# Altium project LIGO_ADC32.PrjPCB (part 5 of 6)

## Sheet AD32_Bipolar2.SchDoc: Dual Analog Supply
size B; Engineer: Daniel Sigg; SheetNumber: 11; SheetTotal: 17
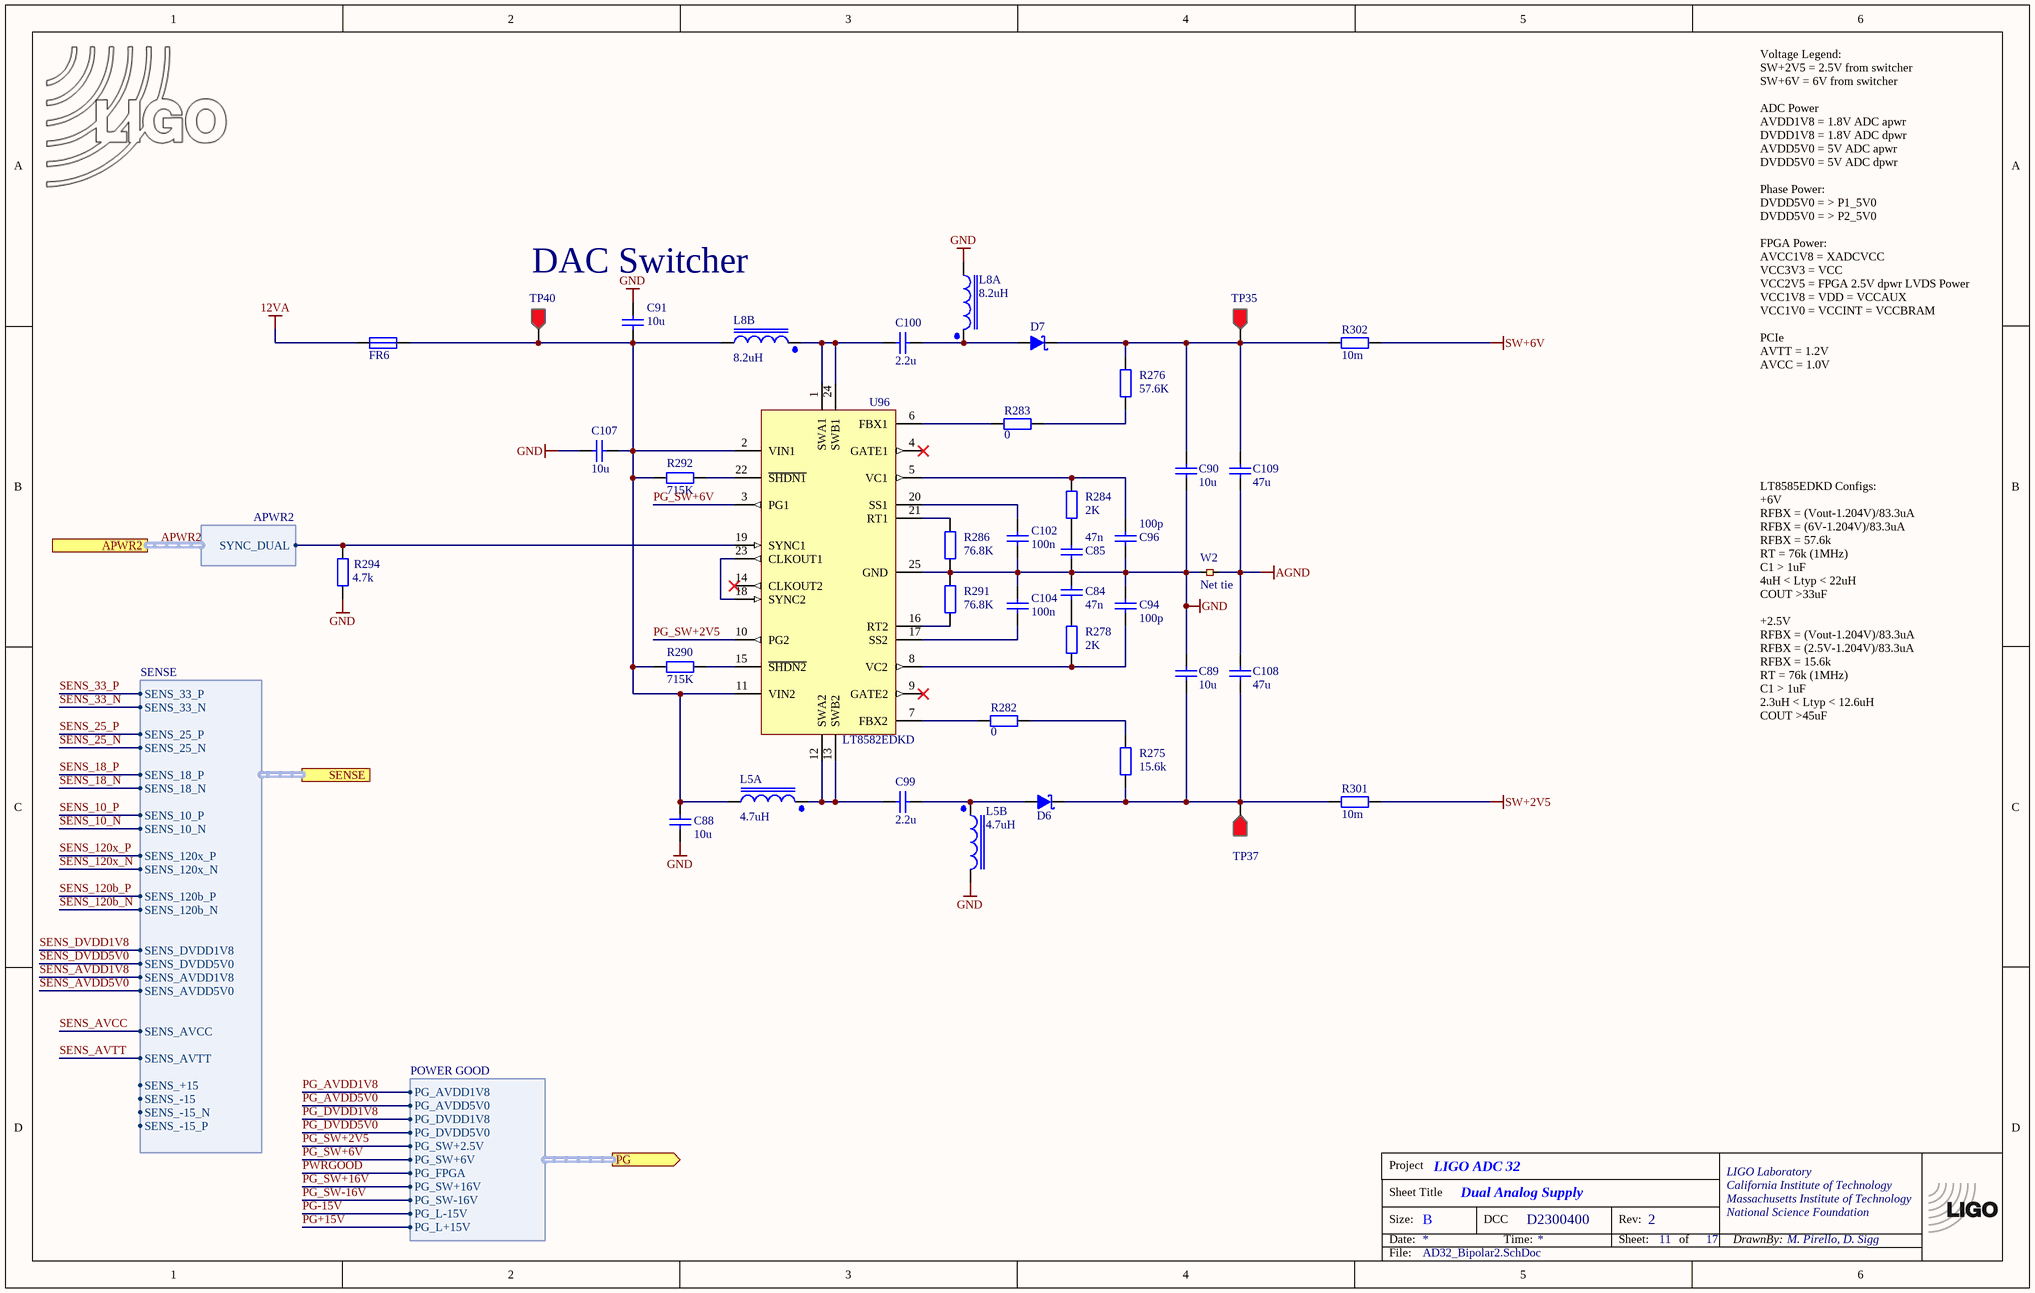
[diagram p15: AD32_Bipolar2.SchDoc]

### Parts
(Parts that share a designator on the sheet are numbered #1, #2 ... from top to bottom, then left to right.)
*?#12  TitleBlock  (value not drawn)  (graphical)
C84  47n  [CC1005-0402]
C85  47n  [CC1005-0402]
C88  10u  [CC3225-1210]
C89  10u  [CC3225-1210]
C90  10u  [CC3225-1210]
C91  10u  [CC3225-1210]
C94  100p  [CC1005-0402]
C96  100p  [CC1005-0402]
C99  2.2u  [CC3216-1206]
C100  2.2u  [CC3216-1206]
C102  100n  [CC1005-0402]
C104  100n  [CC1005-0402]
C107  10u  [CC3225-1210]
C108  47u  [CC5650-2220]
C109  47u  [CC5650-2220]
D6  Schottky DO-PowerDI123  [DO-PowerDI123]  (value not drawn)
D7  Schottky DO-PowerDI123  [DO-PowerDI123]  (value not drawn)
FR6  BLM31PG121  [CC3216-1206]  (value not drawn)
L5  4.7uH  [MSD7342]  (parts A,B of 2)
L8  8.2uH  [MSD7342]  (parts A,B of 2)
LOGO?#6  LIGO logo  [LIGO_LOGO]  (value not drawn)  (graphical)
R275  15.6k  [CR1005-0402]
R276  57.6K  [CR1005-0402]
R278  2K  [CR1005-0402]
R282  0  [CR1005-0402]
R283  0  [CR1005-0402]
R284  2K  [CR1005-0402]
R286  76.8K  [CR1005-0402]
R290  715K  [CR1005-0402]
R291  76.8K  [CR1005-0402]
R292  715K  [CR1005-0402]
R294  4.7k  [CR1005-0402]
R301  10m  [CR1608-0603]
R302  10m  [CR1608-0603]
TP35  Testpoint  [TP1-RED]  (value not drawn)
TP37  Testpoint  [TP1-RED]  (value not drawn)
TP40  Testpoint  [TP1-RED]  (value not drawn)
U96  LT8582EDKD  [DFN-24_DKD]
W2  Net tie  [NETTIE1_SMDTOP]  (net tie, no BOM)

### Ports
APWR2 (harness APWR2), PG (out, harness Power good), SENSE (harness SENSE)

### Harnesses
APWR2: SYNC_DUAL
SENSE: SENS_33_P, SENS_33_N, SENS_25_P, SENS_25_N, SENS_18_P, SENS_18_N, SENS_10_P, SENS_10_N, SENS_120x_P, SENS_120x_N, SENS_120b_P, SENS_120b_N, SENS_DVDD1V8, SENS_DVDD5V0, SENS_AVDD1V8, SENS_+15, SENS_-15, SENS_AVTT, SENS_AVCC, SENS_-15_N, SENS_-15_P, SENS_AVDD5V0
POWER GOOD: PG_AVDD5V0, PG_DVDD1V8, PG_DVDD5V0, PG_SW+2.5V, PG_SW+6V, PG_FPGA, PG_SW+16V, PG_SW-16V, PG_L-15V, PG_L+15V, PG_AVDD1V8

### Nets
12VA: FR6.1
AGND: C108.1 C109.2 W2.2
GND: C84.2 C85.1 C88.1 C89.1 C90.2 C91.2 C94.2 C96.1 C102.1 C104.2 C107.2 L5.4 L8.3 R286.1 R291.2 R294.2 U96.25(GND) W2.1
SW+2V5: R301.1
SW+6V: R302.1
APWR2.SYNC_DUAL: R294.1 U96.19(SYNC1) ; port APWR2.SYNC_DUAL
PG_SW+2V5: U96.10(PG2) ; port PG.PG_SW+2.5V  [project net PG.PG_SW+2.5V]
PG_SW+6V: U96.3(PG1) ; port PG.PG_SW+6V  [project net PG.PG_SW+6V]
NetC84_1: C84.1 R278.2
NetC85_2: C85.2 R284.1
NetC88_2: C88.2 C91.1 C107.1 FR6.2 L5.3 L8.4 R290.2 R292.2 TP40.1 U96.2(VIN1) U96.11(VIN2)
NetC89_2: C89.2 C108.2 D6.2(K) R275.1 R301.2 TP37.1
NetC90_1: C90.1 C109.1 D7.2(K) R276.2 R302.2 TP35.1
NetC94_1: C94.1 R278.1 U96.8(VC2)
NetC96_2: C96.2 R284.2 U96.5(VC1)
NetC99_1: C99.1 D6.1(A) L5.2
NetC99_2: C99.2 L5.1 U96.12(SWA2) U96.13(SWB2)
NetC100_1: C100.1 D7.1(A) L8.1
NetC100_2: C100.2 L8.2 U96.1(SWA1) U96.24(SWB1)
NetC102_2: C102.2 U96.20(SS1)
NetC104_1: C104.1 U96.17(SS2)
NetR275_2: R275.2 R282.1
NetR276_1: R276.1 R283.1
NetR282_2: R282.2 U96.7(FBX2)
NetR283_2: R283.2 U96.6(FBX1)
NetR286_2: R286.2 U96.21(RT1)
NetR290_1: R290.1 U96.15(~{SHDN2})
NetR291_1: R291.1 U96.16(RT2)
NetR292_1: R292.1 U96.22(~{SHDN1})
NetU96_18: U96.18(SYNC2) U96.23(CLKOUT1)

Not connected (* = marked no-connect by the designer): U96 4(GATE1)* 9(GATE2)* 14(CLKOUT2)*

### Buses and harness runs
harness APWR2 = port APWR2

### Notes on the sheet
- DAC Switcher
- Voltage Legend:
  SW+2V5 = 2.5V from switcher
  SW+6V = 6V from switcher
  ADC Power
  AVDD1V8 = 1.8V ADC apwr
  DVDD1V8 = 1.8V ADC dpwr
  AVDD5V0 = 5V ADC apwr
  DVDD5V0 = 5V ADC dpwr
  Phase Power:
  DVDD5V0 = > P1_5V0
  DVDD5V0 = > P2_5V0
  FPGA Power:
  AVCC1V8 = XADCVCC
  VCC3V3 = VCC
  VCC2V5 = FPGA 2.5V dpwr LVDS Power
  VCC1V8 = VDD = VCCAUX
  VCC1V0 = VCCINT = VCCBRAM
  PCIe
  AVTT = 1.2V
  AVCC = 1.0V
- LT8585EDKD Configs:
  +6V
  RFBX = (Vout-1.204V)/83.3uA
  RFBX = (6V-1.204V)/83.3uA
  RFBX = 57.6k
  RT = 76k (1MHz)
  C1 > 1uF
  4uH < Ltyp < 22uH
  COUT >33uF
  +2.5V
  RFBX = (Vout-1.204V)/83.3uA
  RFBX = (2.5V-1.204V)/83.3uA
  RFBX = 15.6k
  RT = 76k (1MHz)
  C1 > 1uF
  2.3uH < Ltyp < 12.6uH
  COUT >45uF

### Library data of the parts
C84 C85 = ChipCap: C0402 47n; Part Number: 0402B473J250CT
C88-C91 C107 = ChipCap: C1210 10u; Part Number: CL32B106KAULNNE
C94 C96 = ChipCap: C0402 100p; Part Number: KGM05ACG1H101JH
C99 C100 = ChipCap: C1206 2.2u; Part Number: C1206C225J5RECAUTO
C102 C104 = ChipCap: C0402 100n; Part Number: CL05B104KA5NNNC
C108 C109 = ChipCap: C2220 47u; Part Number: CGA9N3X7R1C476M230KB
D6 D7 = DIODE_SHOTTKY: Part Number: DFLS230-7
FR6 = BLM31PG121SN1: ferrite bead, 120Ohm at 100MHz, 1206; Part Number: BLM31PG121SN1L
L5 = MSD7342: Shielded Coupled Inductors, MSD7342 series 4.7uH; Part Number: MSD7342-472MLC
L8 = MSD7342: Shielded Coupled Inductors, MSD7342 series 8.2uH; Part Number: MSD7342-822MLC
LOGO?#6 = LIGO_logo
R275 = ChipRes1: R0402 15.6k; Part Number: RN73R1ETTP1562B25
R276 = ChipRes1: R0402 57.6k; Part Number: RT0402DRD0734K8L
R278 R284 = ChipRes1: R0402 2k; Part Number: ERA-2AEB202X
R282 R283 = ChipRes1: R0402 0; Part Number: AC0402FR-070RL
R286 R291 = ChipRes1: R0402 76.8k; Part Number: RT0402DRE0776K8L
R290 R292 = ChipRes1: R0402 715k; Part Number: RC0402FR-07715KL
R294 = ChipRes1: R0402 4.7k; Part Number: ERA-2AED472X
R301 R302 = ChipRes1: R0603 10m; Part Number: CFN0603AFZ-R010ELF
TP35 TP37 TP40 = TP_POSITIVE: Testpoint, red; Part Number: Keystone / 5000
U96 = LT8582: Dual 3A Boost/Inverting/SEPIC DC/DC Converter with Fault Protection; Part Number: LT8582EDKD#PBF
W2 = NetTie1_small: NL

## Sheet AD32_PowerFPGA.SchDoc: FPGA Supply
size B; Engineer: Daniel Sigg; SheetNumber: 9; SheetTotal: 17
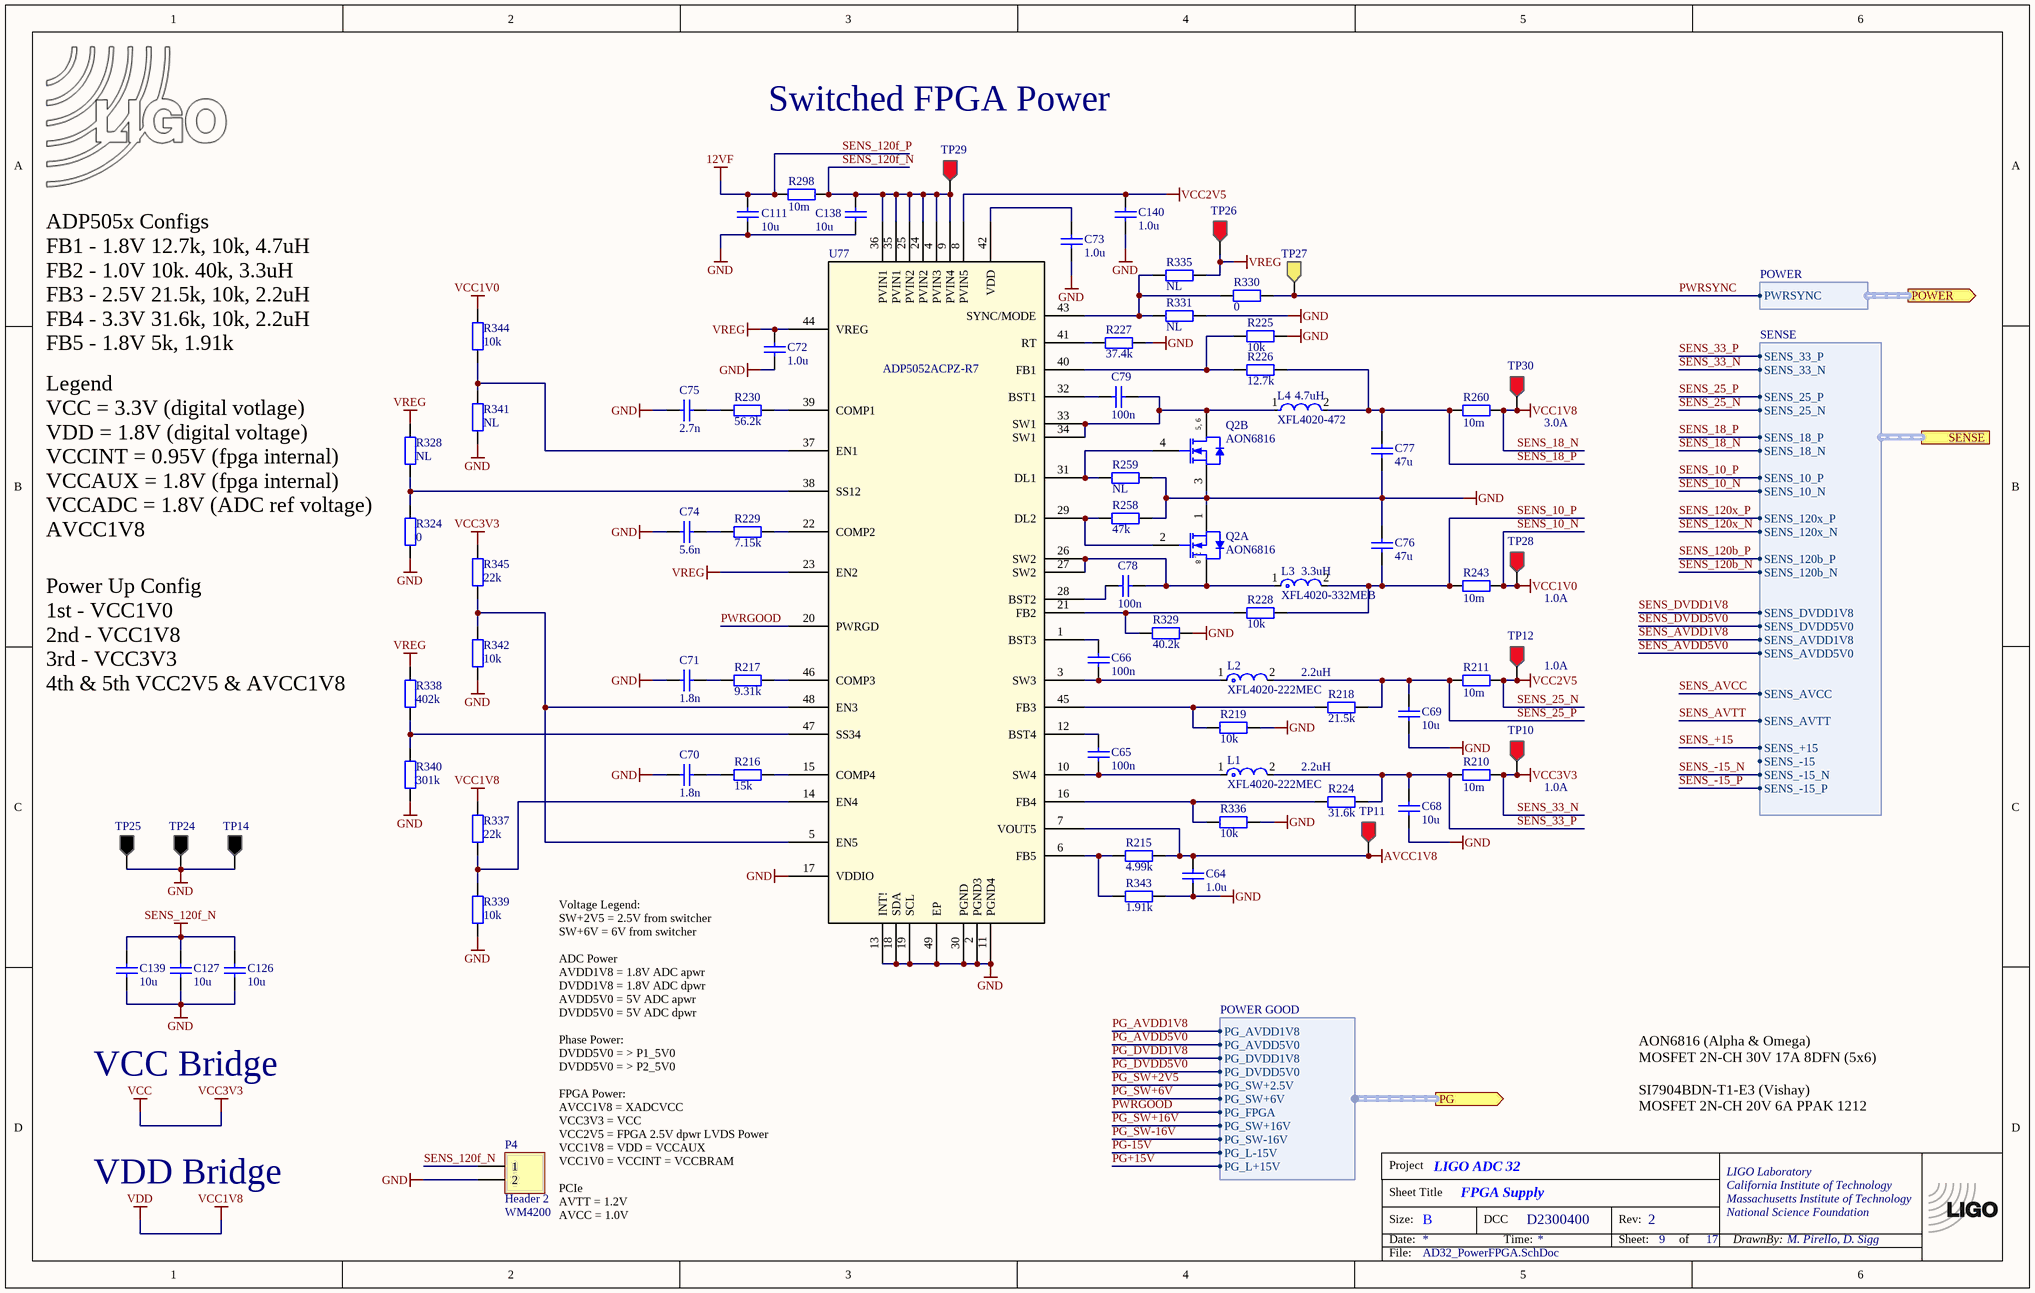
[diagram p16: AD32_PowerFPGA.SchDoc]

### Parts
(Parts that share a designator on the sheet are numbered #1, #2 ... from top to bottom, then left to right.)
*?#13  TitleBlock  (value not drawn)  (graphical)
C64  1.0u  [CC1005-0402]
C65  100n  [CC1005-0402]
C66  100n  [CC1005-0402]
C68  10u  [CC2013-0805]
C69  10u  [CC2013-0805]
C70  1.8n  [CC1005-0402]
C71  1.8n  [CC1005-0402]
C72  1.0u  [CC1005-0402]
C73  1.0u  [CC1005-0402]
C74  5.6n  [CC1005-0402]
C75  2.7n  [CC1005-0402]
C76  47u  [CC3216-1206]
C77  47u  [CC3216-1206]
C78  100n  [CC1005-0402]
C79  100n  [CC1005-0402]
C111  10u  [CC2013-0805]
C126  10u  [CC2013-0805]
C127  10u  [CC2013-0805]
C138  10u  [CC2013-0805]
C139  10u  [CC2013-0805]
C140  1.0u  [CC1005-0402]
L1  XFL4020-222MEC  [FP-XFL4020-MFG]
L2  XFL4020-222MEC  [FP-XFL4020-MFG]
L3  XFL4020-332MEB  [FP-XFL4020-MFG]
L4  XFL4020-472  [FP-XAL40-MFG]
LOGO4#2  LIGO logo  [LIGO_LOGO]  (value not drawn)  (graphical)
P4  Header 2  [WM4200]
Q2  AON6816  [VISH-POWERPAKSO-8_A_V]  (parts A,B of 2)
R210  10m  [CR1608-0603]
R211  10m  [CR1608-0603]
R215  4.99k  [CR1005-0402]
R216  15k  [CR1005-0402]
R217  9.31k  [CR1005-0402]
R218  21.5k  [CR1005-0402]
R219  10k  [CR1005-0402]
R224  31.6k  [CR1005-0402]
R225  10k  [CR1005-0402]
R226  12.7k  [CR1005-0402]
R227  37.4k  [CR1005-0402]
R228  10k  [CR1005-0402]
R229  7.15k  [CR1005-0402]
R230  56.2k  [CR1005-0402]
R243  10m  [CR1608-0603]
R258  47k  [CR1005-0402]
R259  NL  [CR1005-0402]
R260  10m  [CR1608-0603]
R298  10m  [CR1608-0603]
R324  0  [CR1005-0402]
R328  NL  [CR1005-0402]
R329  40.2k  [CR1005-0402]
R330  0  [CR1005-0402]
R331  NL  [CR1005-0402]
R335  NL  [CR1005-0402]
R336  10k  [CR1005-0402]
R337  22k  [CR1005-0402]
R338  402k  [CR1005-0402]
R339  10k  [CR1005-0402]
R340  301k  [CR1005-0402]
R341  NL  [CR1005-0402]
R342  10k  [CR1005-0402]
R343  1.91k  [CR1005-0402]
R344  10k  [CR1005-0402]
R345  22k  [CR1005-0402]
TP10  Testpoint  [TP1-RED]  (value not drawn)
TP11  Testpoint  [TP1-RED]  (value not drawn)
TP12  Testpoint  [TP1-RED]  (value not drawn)
TP14  Testpoint  [TP1-BLK]  (value not drawn)
TP24  Testpoint  [TP1-BLK]  (value not drawn)
TP25  Testpoint  [TP1-BLK]  (value not drawn)
TP26  Testpoint  [TP1-RED]  (value not drawn)
TP27  Testpoint  [TP1-YLW]  (value not drawn)
TP28  Testpoint  [TP1-RED]  (value not drawn)
TP29  Testpoint  [TP1-RED]  (value not drawn)
TP30  Testpoint  [TP1-RED]  (value not drawn)
U77  ADP5052ACPZ-R7  [CP-48-13_L]

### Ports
PG (out, harness Power good), POWER (out, harness POWER), SENSE (harness SENSE)

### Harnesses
POWER: PWRSYNC
SENSE: SENS_33_P, SENS_33_N, SENS_25_P, SENS_25_N, SENS_18_P, SENS_18_N, SENS_10_P, SENS_10_N, SENS_120x_P, SENS_120x_N, SENS_120b_P, SENS_120b_N, SENS_DVDD1V8, SENS_DVDD5V0, SENS_AVDD1V8, SENS_+15, SENS_-15, SENS_AVTT, SENS_AVCC, SENS_-15_N, SENS_-15_P, SENS_AVDD5V0
POWER GOOD: PG_AVDD5V0, PG_DVDD1V8, PG_DVDD5V0, PG_SW+2.5V, PG_SW+6V, PG_FPGA, PG_SW+16V, PG_SW-16V, PG_L-15V, PG_L+15V, PG_AVDD1V8

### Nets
12VF: C111.1 R298.2  [also labelled SENS_120f_P]
AVCC1V8: C64.2 R215.2 TP11.1 U77.7(VOUT5)
GND: C64.1 C68.1 C69.1 C70.1 C71.1 C72.2 C73.1 C74.1 C75.1 C76.2 C77.1 C111.2 C126.2 C127.2 C138.2 C139.2 C140.1 P4.2 Q2.1(S1) Q2.3(S2) R219.2 R225.2 R227.2 R258.2 R259.2 R324.1 R329.2 R331.2 R336.2 R339.1 R340.1 R341.1 R342.1 R343.2 TP14.1 TP24.1 TP25.1 U77.2(PGND3) U77.11(PGND4) U77.13(INT!) U77.17(VDDIO) U77.18(SDA) U77.19(SCL) U77.30(PGND) U77.49(EP)
SENS_120f_N: C126.1 C127.1 C138.1 C139.1 P4.1 R298.1 TP29.1 U77.4(PVIN3) U77.9(PVIN4) U77.24(PVIN2) U77.25(PVIN2) U77.35(PVIN1) U77.36(PVIN1)
VCC: R210.1 R345.2 TP10.1 ; port SENSE.SENS_33_N  [also labelled SENS_33_N, VCC3V3]
VCC1V0: R243.1 R344.2 TP28.1 ; port SENSE.SENS_10_N  [also labelled SENS_10_N]
VCC1V8: R260.1 R337.2 TP30.1 ; port SENSE.SENS_18_N  [also labelled SENS_18_N, VDD]
VCC2V5: C140.2 R211.1 TP12.1 U77.8(PVIN5) ; port SENSE.SENS_25_N  [also labelled SENS_25_N]
VREG: C72.1 R328.2 R335.2 R338.2 TP26.1 U77.23(EN2) U77.44(VREG)
PWRGOOD: U77.20(PWRGD) ; port PG.PG_FPGA  [project net PG.PG_FPGA]
PWRSYNC: R330.2 TP27.1 ; port POWER.PWRSYNC  [project net POWER.PWRSYNC]
SENS_10_P: C76.1 L3.2 R228.2 R243.2 ; port SENSE.SENS_10_P  [project net SENSE.SENS_10_P]
SENS_18_P: C77.2 L4.2 R226.2 R260.2 ; port SENSE.SENS_18_P  [project net SENSE.SENS_18_P]
SENS_25_P: C69.2 L2.2 R211.2 R218.2 ; port SENSE.SENS_25_P  [project net SENSE.SENS_25_P]
SENS_33_P: C68.2 L1.2 R210.2 R224.2 ; port SENSE.SENS_33_P  [project net SENSE.SENS_33_P]
NetC65_1: C65.1 L1.1 U77.10(SW4)
NetC65_2: C65.2 U77.12(BST4)
NetC66_1: C66.1 L2.1 U77.3(SW3)
NetC66_2: C66.2 U77.1(BST3)
NetC70_2: C70.2 R216.1
NetC71_2: C71.2 R217.1
NetC73_2: C73.2 U77.42(VDD)
NetC74_2: C74.2 R229.1
NetC75_2: C75.2 R230.1
NetC78_1: C78.1 U77.28(BST2)
NetC78_2: C78.2 L3.1 Q2.7(D1) Q2.8(D1) U77.26(SW2) U77.27(SW2)
NetC79_1: C79.1 U77.32(BST1)
NetC79_2: C79.2 L4.1 Q2.5(D2) Q2.6(D2) U77.33(SW1) U77.34(SW1)
NetQ2_2: Q2.2(G1) R258.1 U77.29(DL2)
NetQ2_4: Q2.4(G2) R259.1 U77.31(DL1)
NetR215_1: R215.1 R343.1 U77.6(FB5)
NetR216_2: R216.2 U77.15(COMP4)
NetR217_2: R217.2 U77.46(COMP3)
NetR218_1: R218.1 R219.1 U77.45(FB3)
NetR224_1: R224.1 R336.1 U77.16(FB4)
NetR225_1: R225.1 R226.1 U77.40(FB1)
NetR227_1: R227.1 U77.41(RT)
NetR228_1: R228.1 R329.1 U77.21(FB2)
NetR229_2: R229.2 U77.22(COMP2)
NetR230_2: R230.2 U77.39(COMP1)
NetR324_2: R324.2 R328.1 U77.38(SS12)
NetR330_1: R330.1 R331.1 R335.1 U77.43(SYNC/MODE)
NetR337_1: R337.1 R339.2 U77.14(EN4)
NetR338_1: R338.1 R340.2 U77.47(SS34)
NetR341_2: R341.2 R344.1 U77.37(EN1)
NetR342_2: R342.2 R345.1 U77.5(EN5) U77.48(EN3)

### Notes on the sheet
- Switched FPGA Power
- ADP505x Configs
  FB1 - 1.8V 12.7k, 10k, 4.7uH
  FB2 - 1.0V 10k. 40k, 3.3uH
  FB3 - 2.5V 21.5k, 10k, 2.2uH
  FB4 - 3.3V 31.6k, 10k, 2.2uH
  FB5 - 1.8V 5k, 1.91k
- (near L4) 4.7uH
- 3.0A
- Legend
  VCC = 3.3V (digital votlage)
  VDD = 1.8V (digital voltage)
  VCCINT = 0.95V (fpga internal)
  VCCAUX = 1.8V (fpga internal)
  VCCADC = 1.8V (ADC ref voltage)
  AVCC1V8
- (near L3) 3.3uH
- 1.0A
- 2.2uH
- (near TP12) 1.0A
- Power Up Config
  1st - VCC1V0
  2nd - VCC1V8
  3rd - VCC3V3
  4th & 5th VCC2V5 & AVCC1V8
- VCC Bridge
- AON6816 (Alpha & Omega)
  MOSFET 2N-CH 30V 17A 8DFN (5x6)
  SI7904BDN-T1-E3 (Vishay)
  MOSFET 2N-CH 20V 6A PPAK 1212
- VDD Bridge
- (near U77) Voltage Legend:
  SW+2V5 = 2.5V from switcher
  SW+6V = 6V from switcher
  ADC Power
  AVDD1V8 = 1.8V ADC apwr
  DVDD1V8 = 1.8V ADC dpwr
  AVDD5V0 = 5V ADC apwr
  DVDD5V0 = 5V ADC dpwr
  Phase Power:
  DVDD5V0 = > P1_5V0
  DVDD5V0 = > P2_5V0
  FPGA Power:
  AVCC1V8 = XADCVCC
  VCC3V3 = VCC
  VCC2V5 = FPGA 2.5V dpwr LVDS Power
  VCC1V8 = VDD = VCCAUX
  VCC1V0 = VCCINT = VCCBRAM
  PCIe
  AVTT = 1.2V
  AVCC = 1.0V

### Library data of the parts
C64 C72 C73 C140 = ChipCap: C0402 1.0u; Part Number: C0402C105K4PACTU
C65 C66 C78 C79 = ChipCap: C0402 100n; Part Number: CL05B104KA5NNNC
C68 C69 C111 C126 C127 C138 C139 = ChipCap: C0805 10u; Part Number: CL21A106KAYNNNG
C70 C71 = ChipCap: C0402 1.8n; Part Number: C0402C182J3GACTU
C74 = ChipCap: C0402 5.6n; Part Number: GRM1555C1H562GE01D
C75 = ChipCap: C0402 2.7n; Part Number: C0402C272K3RAC7867
C76 C77 = ChipCap: C1206 47u; Part Number: C3216X5R1E476M160AC
L1 L2 = CMP-2000-05090-4: INDUCTOR, 2.2UH, 8A, 20%, 38MHZ, REEL
L3 = CMP-11268-000187-1: Fixed Inductors 3.3Uh Shld 5.2A 38.3mOhms AECQ2; Part Number: XFL4020-332MEC
L4 = CMP-11268-000008-1: INDUCTOR, 4.7uH; Part Number: XFL4020-472MEB
LOGO4#2 = LIGO_logo
P4 = WM4200: Header, 2-Pin
Q2 = CMP-2000-07602-1: Mosfet Array 30V 17A 2.8W Surface Mount 8-DFN (5x6)
R210 R211 R243 R260 R298 = ChipRes1: as R301 on sheet AD32_Bipolar2
R215 = ChipRes1: R0402 4.99k; Part Number: RR0510P-4991-D
R216 = ChipRes1: R0402 15k; Part Number: ERA-2AEB153X
R217 = ChipRes1: R0402 9.31k; Part Number: RT0402BRD079K31L
R218 = ChipRes1: R0402 21.5k; Part Number: RR0510P-2152-D
R219 R225 R228 R336 R339 R342 R344 = ChipRes1: R0402 10k; Part Number: ERA-2AEB103X
R224 = ChipRes1: R0402 31.6k; Part Number: RT0402DRE0731K6L
R226 = ChipRes1: R0402 12.7k; Part Number: RT0402DRE0712K7L
R227 = ChipRes1: R0402 37.4k; Part Number: CR0402-FX-3742GLF
R229 = ChipRes1: R0402 7.15k; Part Number: RT0402BRD077K15L
R230 = ChipRes1: R0402 56.2k; Part Number: RK73H1ETTP5622F
R258 = ChipRes1: R0402 47k; Part Number: RG1005P-473-B-T5
R259 R328 R331 R335 R341 = ChipRes1: R0402 NL
R324 R330 = ChipRes1: R0402 0; Part Number: AC0402FR-070RL
R329 = ChipRes1: R0402 40.2k; Part Number: ERA-2ARC4022X
R337 R345 = ChipRes1: R0402 22k; Part Number: ERA-2AED223X
R338 = ChipRes1: R0402 402k; Part Number: RMCF0402FT402KCT-ND
R340 = ChipRes1: R0402 301k; Part Number: RMCF0402FT301KCT-ND
R343 = ChipRes1: R0402 1.91k; Part Number: RT0402BRD071K91L
TP10-TP12 TP26 TP28-TP30 = TP_POSITIVE: as TP35 on sheet AD32_Bipolar2
TP14 TP24 TP25 = TP_GND: Testpoint, black; Part Number: Keystone / 5001
TP27 = TP_SIGNAL: Testpoint, yellow; Part Number: Keystone / 5004
U77 = ADP5050ACPZ-R7: Artix 7 Power Supply; Part Number: ADP5050ACPZ-R7CT-ND

## Sheet AD32_PHASE2.SchDoc: VCO & Phase Detector
size B; DocumentNumber: 1; Revision: C; SheetNumber: 3; SheetTotal: 17; SPICEModelCacheGRPSJKPR: <root> / <DocumentId>GRPSJKPR</DocumentId> / <CacheFrame Number="0"> / <Model Name="op284f" Kind="CKT"> / <Text>* OP284F SPICE Macro-model              11/95 / Rev. B / *                                       ARG / ADSC / * / * Revision History: / * / *     Rev. B / * Changed the short-circuit output current limit from +/- 7.5mA / * to +/- 6.5mA to reflect final data sheet limits. / * / * Changed Vos spec to conform to final data sheet value of / * 125uV, up from 50uV. / * / * / * This version of the OP284 model simulates the worst-case / * parameters of the 'F' grade.  The worst-case parameters / * used correspond to those in the data sheet. / * / * Copyright 1993 by Analog Devices / * / * Refer to "README.DOC" file for License Statement. Use of this model / * indicates your acceptance of the terms and provisions in the License / * Statement. / * / * Node assignments / *                non-inverting input / *                ¦   inverting input / *                ¦   ¦   positive supply / *                ¦   ¦   ¦   negative supply / *                ¦   ¦   ¦   ¦   output / *                ¦   ¦   ¦   ¦   ¦ / .SUBCKT OP284F   1   2   99  50  45 / * / * INPUT STAGE / * / Q1   5    2    3    QIN 1 / Q2   6    11   3    QIN 1 / Q3   7    2    4    QIP 1 / Q4   8    11   4    QIP 1 / DC1  2    11   DC / DC2  11   2    DC / Q5   4    9    99   QIP 1 / Q6   9    9    99   QIP 1 / Q7   3    10   50   QIN 1 / Q8   10   10   50   QIN 1 / R1   99   5    4E3 / R2   99   6    4E3 / R3   7    50   4E3 / R4   8    50   4E3 / IREF 9    10   50.5E-6 / EOS  1    11   POLY(2) (22,98) (14,98) -125E-6 501.2E-3 1 / IOS  2    1    25E-9 / CIN  1    2    2E-12 / GN1  98   1    17 98 1E-3 / GN2  98   2    23 98 1E-3 / * / * VOLTAGE NOISE SOURCE WITH FLICKER NOISE / * / VN1  13   98   DC 2 / VN2  98   15   DC 2 / DN1  13   14   DEN / DN2  14   15   DEN / * / * CURRENT NOISE SOURCE WITH FLICKER NOISE / * / VN3  16   98   DC 2 / VN4  98   18   DC 2 / DN3  16   17   DIN / DN4  17   18   DIN / * / * 2ND CURRENT NOISE SOURCE WITH FLICKER NOISE / * / VN5  19   98   DC 2 / VN6  98   24   DC 2 / DN5  19   23   DIN / DN6  23   24   DIN / * / * GAIN STAGE / * / EREF 98   0    POLY(2) (99,0) (50,0) 0 0.5 0.5 / G1   98   20   POLY(2) (6,5) (8,7) 0 0.5E-3 0.5E-3 / R9   20   98   1E3 / * / * COMMON MODE STAGE WITH ZERO AT 5KHZ / * / ECM  98   21   POLY(2) (1,98) (2,98) 0 0.5 0.5 / R10  21   22   1 / R11  22   98   100E-6 / C4   21   22   31.756E-6 / * / * NEGATIVE ZERO AT 20MHZ / * / E1   27   98   20 98 1 / R17  27   28   1 / R18  28   98   1E-6 / C8   25   26   7.958E-9 / ENZ  25   98   27 28 1 / VNZ  26   98   DC 0 / FNZ  27   28   VNZ -1 / * / * POLE AT 40MHZ / * / G4   98   29   28 98 1E6 / R19  29   98   1 / C9   29   98   3.979E-9 / * / * POLE AT 40MHZ / * / G5   98   30   29 98 1 / R20  30   98   1 / C10  30   98   3.979E-9 / * / * OUTUT STAGE / * / ISY  99   50   0.526E-3 / GIN  50   31   POLY(1) (30,98) 0.862574E-6 511.855E-6 / RIN  31   50   2.75E6 / VB   99   32   0.7 / Q11  32   31   33   QON 1 / R21  33   34   4.5E3 / I1   34   50   50E-6 / R22  99   35   6E3 / Q12  36   36   35   QOP 1 / I2   36   50   50E-6 / R23  99   37   2.6E3 / R24  34   38   5E3 / Q13  39   36   37   QOP 1 / Q14  39   38   40   QON 1.5 / R25  40   50   40 / Q15  39   39   41   QON 1 / R26  41   42   1E3 / R27  99   43   220 / Q16  44   44   43   QOP 1.5 / Q17  44   39   42   QON 1 / R28  42   50   2E3 / VSCP 99   97   DC 0 / FSCP 46   99   VSCP 1 / RSCP 46   99   125 / Q20  44   46   99   QOP 1 / Q18  45   44   97   QOP 4.5 / Q19  45   34   51   QON 4.5 / VSCN 51   50   DC 0 / FSCN 50   47   VSCN 1 / RSCN 47   50   122 / Q21  34   47   50   QON 1 / CC2  31   45   20E-12 / CF1  31   34   15E-12 / CF2  31   42   15E-12 / CO1  34   45   15E-12 / CO2  42   45   5E-12 / D3   45   99   DX / D4   50   45   DX / .MODEL DC D(IS=130E-21) / .MODEL DX D() / .MODEL DEN D(RS=100 KF=12E-15 AF=1) / .MODEL DIN D(RS=5.358 KF=56E-15 AF=1) / .MODEL QIN NPN(BF=250 VA=200 IS=0.5E-16) / .MODEL QIP PNP(BF=60 VA=100 IS=0.5E-16) / .MODEL QON NPN(BF=200 VA=200 IS=0.5E-16 RC=140) / .MODEL QOP PNP(BF=200 VA=200 IS=0.5E-16 RC=210) / .ENDS</Text> / </Model> / </CacheFrame> / </root>
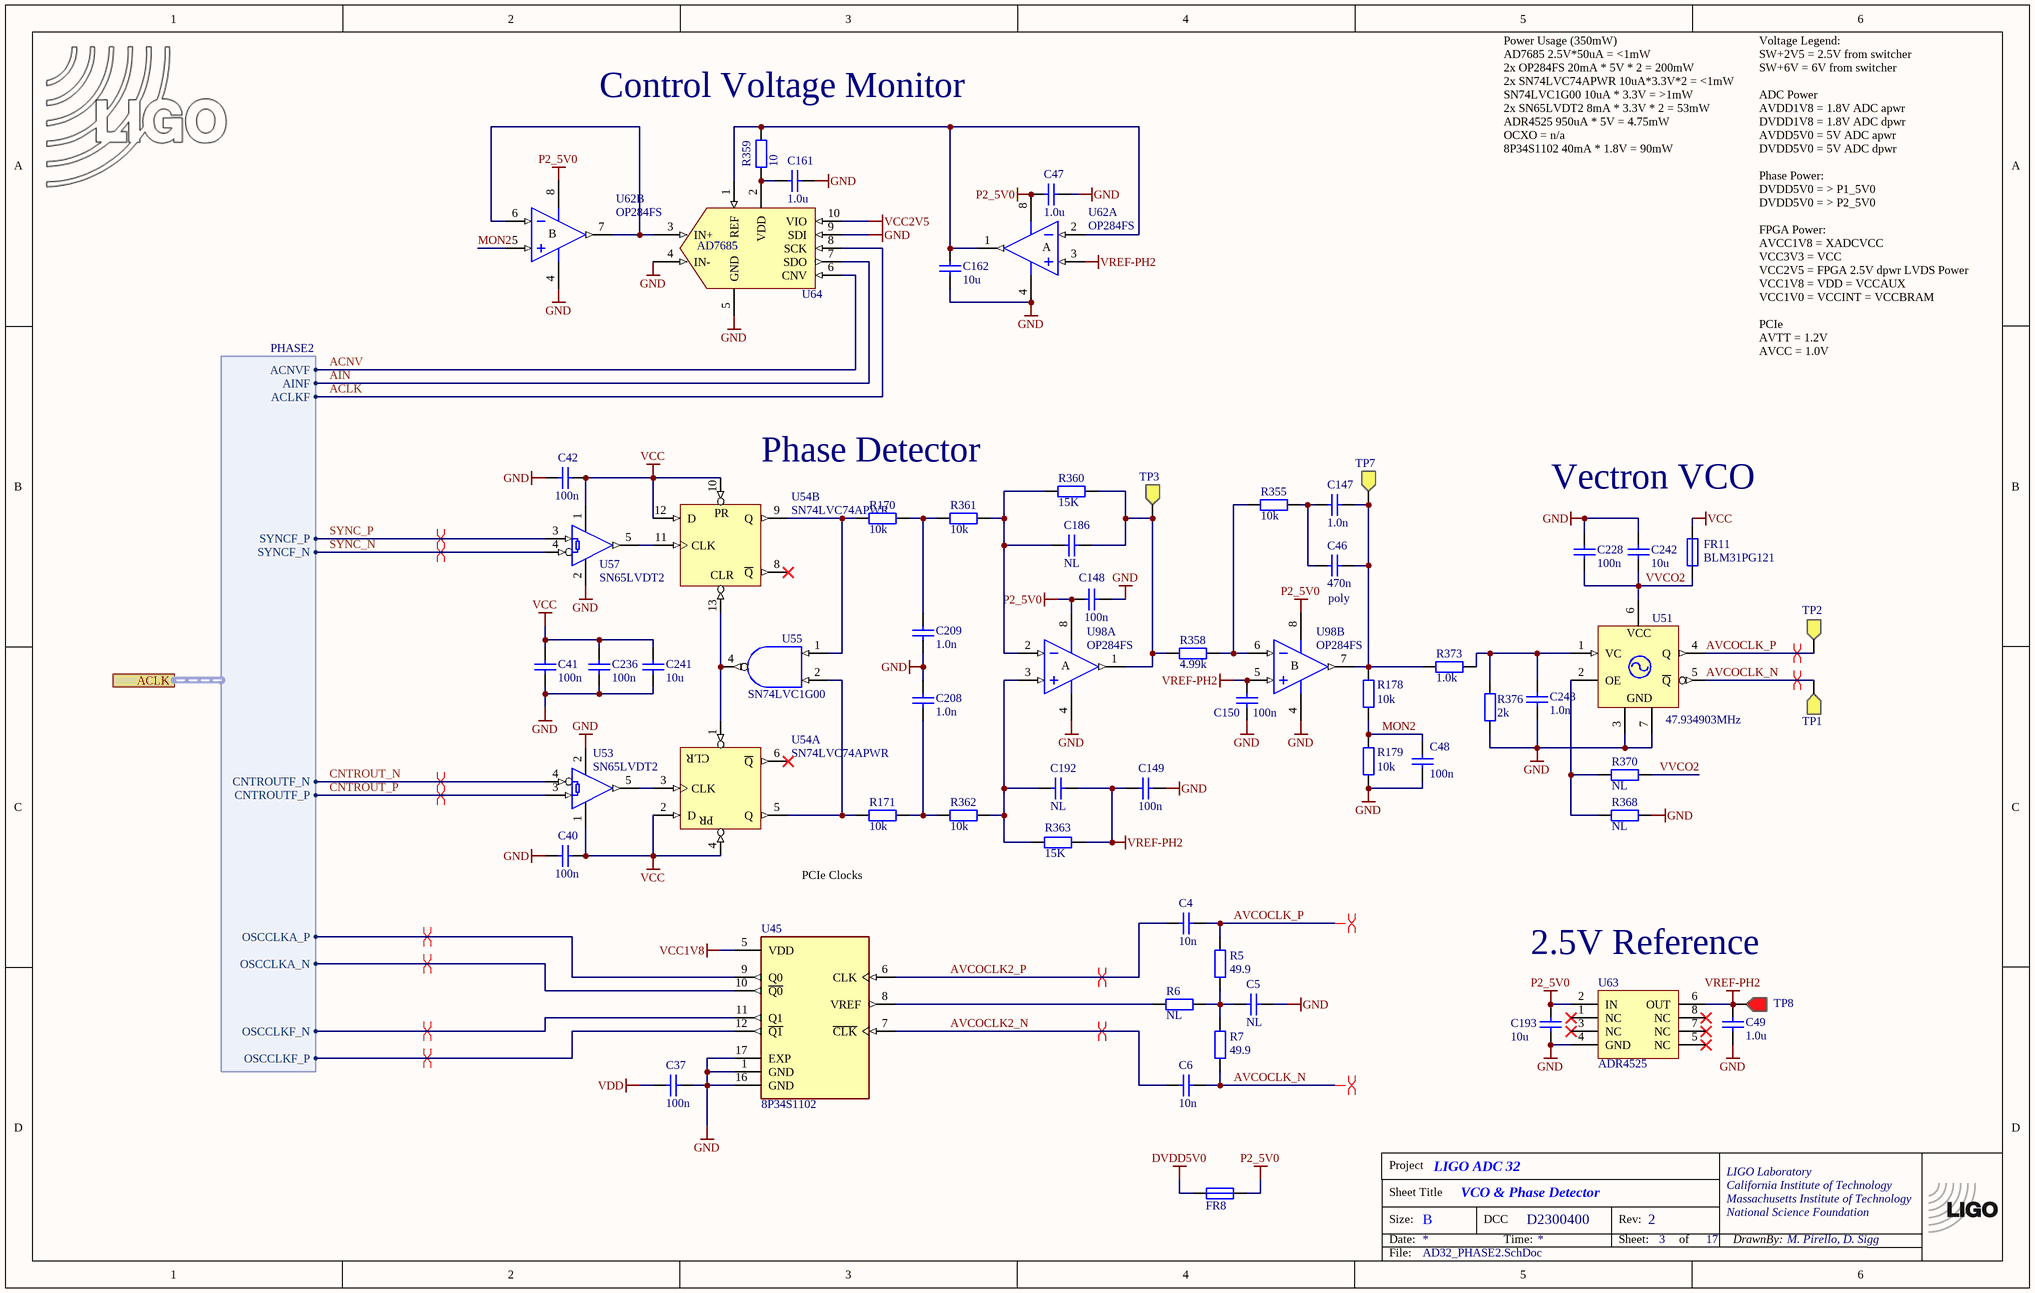
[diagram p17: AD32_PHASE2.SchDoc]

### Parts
(Parts that share a designator on the sheet are numbered #1, #2 ... from top to bottom, then left to right.)
*?#14  TitleBlock  (value not drawn)  (graphical)
C4  10n  [CC1005-0402]
C5  NL  [CC1005-0402]
C6  10n  [CC1005-0402]
C37  100n  [CC2013-0805]
C40  100n  [CC1005-0402]
C41  100n  [CC1005-0402]
C42  100n  [CC1005-0402]
C46  470n  [ECQPZ085045-5.0]
C47  1.0u  [CC1608-0603]
C48  100n  [CC1005-0402]
C49  1.0u  [CC1608-0603]
C147  1.0n  [CC1005-0402]
C148  100n  [CC1005-0402]
C149  100n  [CC1005-0402]
C150  100n  [CC1005-0402]
C161  1.0u  [CC1608-0603]
C162  10u  [CC2013-0805]
C186  NL  [CC2013-0805]
C192  NL  [CC2013-0805]
C193  10u  [CC2013-0805]
C208  1.0n  [CC1005-0402]
C209  1.0n  [CC1005-0402]
C228  100n  [CC1005-0402]
C236  100n  [CC1005-0402]
C241  10u  [CC2013-0805]
C242  10u  [CC2013-0805]
C248  1.0n  [CC1005-0402]
FR8  BLM31PG121  [CC3216-1206]  (value not drawn)
FR11  BLM31PG121  [CC3216-1206]
LOGO2#3  LIGO logo  [LIGO_LOGO]  (value not drawn)  (graphical)
R5  49.9  [CR1005-0402]
R6  NL  [CR1005-0402]
R7  49.9  [CR1005-0402]
R170  10k  [CR1005-0402]
R171  10k  [CR1005-0402]
R178  10k  [CR1005-0402]
R179  10k  [CR1005-0402]
R355  10k  [CR1005-0402]
R358  4.99k  [CR1005-0402]
R359  10  [CR1005-0402]
R360  15K  [CR1005-0402]
R361  10k  [CR1005-0402]
R362  10k  [CR1005-0402]
R363  15K  [CR1005-0402]
R368  NL  [CR1005-0402]
R370  NL  [CR1005-0402]
R373  1.0k  [CR1005-0402]
R376  2k  [CR1005-0402]
TP1  Testpoint  [TP2]  (value not drawn)
TP2  Testpoint  [TP2]  (value not drawn)
TP3  Testpoint  [TP1-YLW]  (value not drawn)
TP7  Testpoint  [TP1-YLW]  (value not drawn)
TP8  Testpoint  [TP1-RED]  (value not drawn)
U45  8P34S1102  [QFN50P300X300X100-17N]
U51  47.934903MHz  [BomarSiTime]
U53  SN65LVDT2  [SO-G5/E2.4]
U54  SN74LVC74APWR  [TSSOP14]  (parts A,B of 2)
U55  SN74LVC1G00  [SO-G5/E2.4]
U57  SN65LVDT2  [SO-G5/E2.4]
U62  OP284FS  [SO-8_N]  (parts A,B of 2)
U63  ADR4525  [SO-G8]
U64  AD7685  [TSSO3x5-G10]
U98  OP284FS  [SO-8_N]  (parts A,B of 2)

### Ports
ACLK (harness PHASE2)

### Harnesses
PHASE2: OSCCLKA_N, OSCCLKA_P, CNTROUTF_N, CNTROUTF_P, SYNCF_N, SYNCF_P, ACLKF, ACNVF, AINF, OSCCLKF_P, OSCCLKF_N

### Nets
DVDD5V0: FR8.2
GND: C5.2 C37.1 C40.1 C41.1 C42.1 C47.1 C48.1 C49.1 C148.1 C149.1 C150.1 C161.1 C162.2 C193.2 C208.1 C209.2 C228.1 C236.1 C241.2 C242.1 C248.2 R179.2 R368.2 R376.2 U45.1(GND) U45.16(GND) U45.17(EXP) U51.3(GND1) U51.7(GND2) U53.2(GND) U54.7(GND) U55.3(GND) U57.2(GND) U62.4(V-) U63.4(GND) U64.4(IN-) U64.5(GND) U64.9(SDI) U98.4(V-)
P2_5V0: C47.2 C148.2 C193.1 FR8.1 U62.8(V+) U63.2(IN) U98.8(V+)
VCC: C40.2 C41.2 C42.2 C236.2 C241.1 FR11.2 U53.1(VCC) U54.2(D) U54.4(PR) U54.10(PR) U54.12(D) U54.14(VCC) U55.5(VCC) U57.1(VCC)
VCC1V8: C37.2 U45.5(VDD)  [also labelled VDD]
VCC2V5: U64.10(VIO)
VREF-PH2: C49.2 C149.2 C150.2 C192.1 R363.2 TP8.1 U62.3(IN+) U63.6(OUT) U98.5(IN+)
ACLK: U64.8(SCK) ; port ACLK.ACLKF  [project net ACLK.ACLKF]
ACLK.OSCCLKA_N: U45.10(~{Q0}) ; port ACLK.OSCCLKA_N
ACLK.OSCCLKA_P: U45.9(Q0) ; port ACLK.OSCCLKA_P
ACLK.OSCCLKF_N: U45.11(Q1) ; port ACLK.OSCCLKF_N
ACLK.OSCCLKF_P: U45.12(~{Q1}) ; port ACLK.OSCCLKF_P
ACNV: U64.6(CNV) ; port ACLK.ACNVF  [project net ACLK.ACNVF]
AIN: U64.7(SDO) ; port ACLK.AINF  [project net ACLK.AINF]
AVCOCLK2_N: C6.1 U45.7(~{CLK})
AVCOCLK2_P: C4.1 U45.6(CLK)
AVCOCLK_N: C6.2 R7.1 TP1.1 U51.5(~{Q})
AVCOCLK_P: C4.2 R5.2 TP2.1 U51.4(Q)
CNTROUT_N: U53.4(B) ; port ACLK.CNTROUTF_N  [project net ACLK.CNTROUTF_N]
CNTROUT_P: U53.3(A) ; port ACLK.CNTROUTF_P  [project net ACLK.CNTROUTF_P]
MON2: C48.2 R178.2 R179.1 U62.5(IN+)
SYNC_N: U57.4(B) ; port ACLK.SYNCF_N  [project net ACLK.SYNCF_N]
SYNC_P: U57.3(A) ; port ACLK.SYNCF_P  [project net ACLK.SYNCF_P]
VVCO2: C228.2 C242.2 FR11.1 R370.2 U51.6(VDD)
NetC5_1: C5.1 R5.1 R6.1 R7.2
NetC46_1: C46.1 C147.2 R355.2
NetC46_2: C46.2 C147.1 R178.1 R373.2 TP7.1 U98.7(OUT)
NetC161_2: C161.2 R359.1 U64.2(VDD)
NetC162_1: C162.1 R359.2 U62.1(OUT) U62.2(IN-) U64.1(REF)
NetC186_1: C186.1 R358.1 R360.2 TP3.1 U98.1(OUT)
NetC186_2: C186.2 R360.1 R361.2 U98.2(IN-)
NetC192_2: C192.2 R362.2 R363.1 U98.3(IN+)
NetC208_2: C208.2 R171.2 R362.1
NetC209_1: C209.1 R170.2 R361.1
NetC248_1: C248.1 R373.1 R376.1 U51.1(VC)
NetR6_2: R6.2 U45.8(VREF)
NetR170_1: R170.1 U54.9(Q) U55.1
NetR171_1: R171.1 U54.5(Q) U55.2
NetR355_1: R355.1 R358.2 U98.6(IN-)
NetR368_1: R368.1 R370.1 U51.2(OE)
NetU53_5: U53.5(R) U54.3(CLK)
NetU54_1: U54.1(CLR) U54.13(CLR) U55.4
NetU54_11: U54.11(CLK) U57.5(R)
NetU62_6: U62.6(IN-) U62.7(OUT) U64.3(IN+)

Not connected (* = marked no-connect by the designer): U54 6(~{Q})* 8(~{Q})*; U63 1(NC)* 3(NC)* 5(NC)* 7(NC)* 8(NC)*

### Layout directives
differential pair: ACLK.CNTROUTF_N, ACLK.CNTROUTF_P, ACLK.OSCCLKF_N, ACLK.OSCCLKF_P, ACLK.SYNCF_N, ACLK.SYNCF_P, AVCOCLK_N, AVCOCLK_P
differential pair; differential pair class PCIe Clocks: ACLK.OSCCLKA_N, ACLK.OSCCLKA_P, AVCOCLK2_N, AVCOCLK2_P

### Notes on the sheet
- (near R359) Control Voltage Monitor
- Power Usage (350mW)
  AD7685 2.5V*50uA = <1mW
  2x OP284FS 20mA * 5V * 2 = 200mW
  2x SN74LVC74APWR 10uA*3.3V*2 = <1mW
  SN74LVC1G00 10uA * 3.3V = >1mW
  2x SN65LVDT2 8mA * 3.3V * 2 = 53mW
  ADR4525 950uA * 5V = 4.75mW
  OCXO = n/a
  8P34S1102 40mA * 1.8V = 90mW
- Voltage Legend:
  SW+2V5 = 2.5V from switcher
  SW+6V = 6V from switcher
  ADC Power
  AVDD1V8 = 1.8V ADC apwr
  DVDD1V8 = 1.8V ADC dpwr
  AVDD5V0 = 5V ADC apwr
  DVDD5V0 = 5V ADC dpwr
  Phase Power:
  DVDD5V0 = > P1_5V0
  DVDD5V0 = > P2_5V0
  FPGA Power:
  AVCC1V8 = XADCVCC
  VCC3V3 = VCC
  VCC2V5 = FPGA 2.5V dpwr LVDS Power
  VCC1V8 = VDD = VCCAUX
  VCC1V0 = VCCINT = VCCBRAM
  PCIe
  AVTT = 1.2V
  AVCC = 1.0V
- Phase Detector
- Vectron VCO
- poly
- PCIe Clocks
- 2.5V Reference

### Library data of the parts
C4 C6 = ChipCap: C0402 10n; Part Number: CC0402KRX7R9BB103
C5 = ChipCap: C0402 NL
C37 = ChipCap: C0805 100n; Part Number: KGM21NR71H104KM
C40-C42 C48 C148-C150 C228 C236 = ChipCap: C0402 100n; Part Number: CL05B104KA5NNNC
C46 = CapPolypropylene ECQPZ: Polypropylene Film Capacitor, radial lead; Part Number: 399-13063-ND
C47 C49 C161 = ChipCap: C0603 1.0u; Part Number: CL10B105KA8NNNC
C147 C208 C209 C248 = ChipCap: C0402 1.0n; Part Number: 0402N102J250CT
C162 C193 C241 C242 = ChipCap: C0805 10u; Part Number: CL21A106KAYNNNG
C186 C192 = ChipCap: C0805 NL
FR8 FR11 = BLM31PG121SN1: as FR6 on sheet AD32_Bipolar2
LOGO2#3 = LIGO_logo
R5 R7 = ChipRes1: R0402 49.9; Part Number: ERA-2AEB49R9X
R6 R368 R370 = ChipRes1: R0402 NL
R170 R171 R178 R179 R355 R361 R362 = ChipRes1: R0402 10k; Part Number: ERA-2AEB103X
R358 = ChipRes1: R0402 4.99k; Part Number: RR0510P-4991-D
R359 = ChipRes1: R0402 10; Part Number: RP73PF1E10RBTD
R360 R363 = ChipRes1: R0402 15k; Part Number: ERA-2AEB153X
R373 = ChipRes1: R0402 1.0k; Part Number: RT0402BRD071KL
R376 = ChipRes1: R0402 2k; Part Number: ERA-2AEB202X
TP1 TP2 = TP_SIGNAL: Part Number: Keystone / 5017
TP3 TP7 = TP_SIGNAL: as TP27 on sheet AD32_PowerFPGA
TP8 = TP_POSITIVE: as TP35 on sheet AD32_Bipolar2
U45 = 8P34S1102: 1:2 LVDS 1.8V / 2.5V Fanout Buffer for 1PPS and High-Speed Clocks; Part Number: 800-2756-ND
U51 = BomarSiTime: Voltage controlled crystal oscillator Bomar 14.3 x 8.7mm and SiTime 7.0 x 5.0mm; Part Number: B1815-BA0S36LK-47.934903; Alternate Part 1: sit3372ai-1e2-xxxx000.fp0000f
U53 U57 = SN65LVDT2DBV: Single LVDS Receiver with 100 Ohm termination; Part Number: 296-6896-1-ND
U54 = 74F74PC: Dual D-Type Positive Edge-Triggered Flip-Flop
U55 = SN74LVC1G00: Part Number: 74LVC1G00W5-7
U62 U98 = OP284FS: Precision Rail-to-Rail Input and Output Operational Amplifier; Part Number: OP284FSZ-REEL7
U63 = ADR292ER: Low-Noise Micropower Precision Voltage Reference; Part Number: ADR425ARZ-ND
U64 = AD7685: 16 bit ADC, 250kSPS, pseudo differential, serial; Part Number: AD7685BRMZRL7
